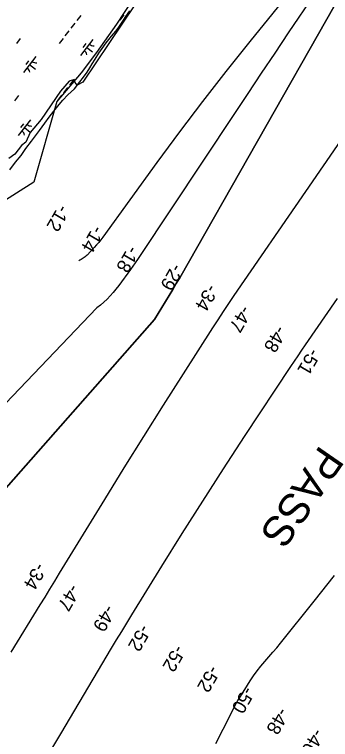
# Model space of a CAD drawing. Extents: x 3888273 to 3909528, y 158682 to 181032.
# Drawn here: x 3899572 to 3900353, y 169134 to 170923 of the extents above; entities that cross this region are included whole.
import ezdxf

# ---------------------------------------------------------------- set-up
doc = ezdxf.new("R2010")
doc.units = 0
for name, color, linetype in [('V-RIVR-EDGE', 7, 'Continuous'), ('V-RIVR-IDEN', 7, 'Continuous'), ('V-RIVR-RANG', 7, 'Continuous'), ('V-RRAP-FSHR', 7, 'Continuous'), ('V-TOPO-DPTH', 7, 'Continuous'), ('V-TOPO-MAJR', 7, 'Continuous'), ('V-TOPO-MINR', 7, 'Continuous'), ('V-WETL-SWMP', 7, 'Continuous')]:
    doc.layers.add(name, color=color, linetype=linetype)

msp = doc.modelspace()

# ---------------------------------------------------------------- linework, layer by layer
at = {"layer": 'V-RIVR-EDGE'}
msp.add_lwpolyline([(3900395.1, 172036.4), (3900253.9, 171678.7), (3900157.2, 171435.2), (3900080.1, 171257.8), (3900063.4, 171231.7), (3900050.4, 171212.2), (3900019.7, 171182.5), (3899994.6, 171143.5), (3899976, 171098.9), (3899921.2, 171023.6), (3899901.7, 170995.7), (3899740.9, 170756), (3899727, 170748.5), (3899721.4, 170755.1), (3899720.5, 170762.5), (3899706.6, 170758.8), (3899685.2, 170733.7), (3899637.8, 170664), (3899610.8, 170631.5), (3899599.7, 170608.2), (3899589.5, 170599.9), (3899572.7, 170578.5), (3899557.9, 170567.4)], dxfattribs=at)
at = {"layer": 'V-RRAP-FSHR'}
msp.add_lwpolyline([(3900345, 171972), (3900308.9, 171879.2), (3900156.1, 171475.9), (3900123.1, 171393.6), (3900080.8, 171288.9), (3899961.8, 171111.1), (3899882.3, 170989.1), (3899823.6, 170898.7), (3899774.2, 170829.5), (3899736.4, 170779.3), (3899676.3, 170708), (3899619.4, 170509.4), (3899413.7, 170379.3)], dxfattribs=at)
at = {"layer": 'V-TOPO-DPTH'}
for points in [[(3899439.6, 169630.1), (3899917.5, 170170.5), (3899935.8, 170199.9), (3899963.2, 170244.7), (3899967.5, 170251.8), (3899971.7, 170258.9), (3899975.9, 170266.1), (3899980.1, 170273.2), (3900364.6, 170948), (3900888.2, 171578.3), (3900889.3, 171579.9), (3900890.3, 171581.6), (3900892.5, 171584.8), (3900894.6, 171588.1), (3900895.7, 171589.7), (3900896.8, 171591.3), (3901374.6, 172277.6)], [(3899439.6, 169630.1), (3899917.5, 170170.5), (3899935.8, 170199.9), (3899963.2, 170244.7), (3899967.5, 170251.8), (3899971.7, 170258.9), (3899975.9, 170266.1), (3899980.1, 170273.2), (3900364.6, 170948), (3900888.2, 171578.3), (3900889.3, 171579.9), (3900890.3, 171581.6), (3900892.5, 171584.8), (3900894.6, 171588.1), (3900895.7, 171589.7), (3900896.8, 171591.3), (3901374.6, 172277.6)], [(3900313.7, 170974.2), (3900248.6, 170877.6), (3900215.2, 170827.9), (3900181.8, 170778.1), (3900148.6, 170728.2), (3900115.3, 170678.4), (3899881.1, 170326.1), (3899875.6, 170318), (3899870.1, 170309.9), (3899864.4, 170301.9), (3899858.7, 170294), (3899829.4, 170254.2), (3899822.6, 170245.4), (3899815.6, 170236.9), (3899808.2, 170228.7), (3899800.5, 170220.7), (3899792.5, 170213.1), (3899784.2, 170205.7), (3899775.7, 170198.7), (3899322.9, 169727)], [(3900378.7, 170612.9), (3900334.8, 170549.4), (3900290.9, 170485.9), (3900114.1, 170229.3), (3900100.7, 170209.5), (3900087.4, 170189.8), (3900074.3, 170169.8), (3900061.3, 170149.8), (3899988.5, 170036.1), (3899939.4, 169959), (3899890.7, 169881.7), (3899842.3, 169804.1), (3899794.3, 169726.4), (3899682.5, 169544), (3899670.5, 169524.4), (3899658.6, 169504.9), (3899646.6, 169485.4), (3899634.6, 169465.9), (3899562.8, 169349.4)], [(3900378.7, 170612.9), (3900334.8, 170549.4), (3900290.9, 170485.9), (3900114.1, 170229.3), (3900100.7, 170209.5), (3900087.4, 170189.8), (3900074.3, 170169.8), (3900061.3, 170149.8), (3899988.5, 170036.1), (3899939.4, 169959), (3899890.7, 169881.7), (3899842.3, 169804.1), (3899794.3, 169726.4), (3899682.5, 169544), (3899670.5, 169524.4), (3899658.6, 169504.9), (3899646.6, 169485.4), (3899634.6, 169465.9), (3899562.8, 169349.4)]]:
    msp.add_lwpolyline(points, dxfattribs=at)
at = {"layer": 'V-TOPO-MAJR'}
for points in [[(3900369.6, 170222.2), (3900290.5, 170107.8), (3900281.3, 170094.4), (3900272.1, 170081), (3900263.1, 170067.5), (3900254.1, 170054), (3900139.9, 169881.2), (3900088, 169801.9), (3900036.5, 169722.2), (3899985.8, 169642.1), (3899935.5, 169561.7), (3899861.1, 169441.4), (3899848.5, 169420.9), (3899835.9, 169400.4), (3899823.5, 169379.8), (3899811.1, 169359.1), (3899685.2, 169147.8), (3899642.1, 169075.2)], [(3900069.6, 169123.9), (3900087.6, 169159.2), (3900118.1, 169219), (3900120.9, 169224.4), (3900123.8, 169229.7), (3900126.9, 169235), (3900130.1, 169240.1), (3900154.5, 169278.6), (3900162.8, 169291), (3900171.6, 169303.1), (3900180.9, 169314.8), (3900190.6, 169326.2), (3900200.5, 169337.5), (3900210.3, 169348.9), (3900219.9, 169360.4), (3900229.4, 169371.9), (3900312.7, 169474.9), (3900362.9, 169538.7)]]:
    msp.add_lwpolyline(points, dxfattribs=at)
at = {"layer": 'V-TOPO-MINR'}
for points in [[(3901374.6, 172277.6), (3900896.8, 171591.3), (3900895.7, 171589.7), (3900894.6, 171588.1), (3900892.5, 171584.8), (3900890.3, 171581.6), (3900889.3, 171579.9), (3900888.2, 171578.3), (3900364.6, 170948), (3899980.1, 170273.2), (3899975.9, 170266.1), (3899971.7, 170258.9), (3899967.5, 170251.8), (3899963.2, 170244.7), (3899935.8, 170199.9), (3899917.5, 170170.5), (3899439.6, 169630.1)], [(3900267.2, 170996.8), (3900153.3, 170856.4), (3900094.5, 170782.7), (3900036.6, 170708.5), (3899979.8, 170633.3), (3899923.9, 170557.5), (3899790.3, 170373.7), (3899785.3, 170367.1), (3899780.1, 170360.6), (3899774.7, 170354.3), (3899769.1, 170348.2), (3899751.2, 170329.4), (3899748.9, 170327.2), (3899746.6, 170325.2), (3899744.1, 170323.4), (3899741.5, 170321.7), (3899738.9, 170320.1), (3899736.2, 170318.4), (3899733.7, 170316.7), (3899731.1, 170314.9)], [(3900313.7, 170974.2), (3900248.6, 170877.6), (3900215.2, 170827.9), (3900181.8, 170778.1), (3900148.6, 170728.2), (3900115.3, 170678.4), (3899881.1, 170326.1), (3899875.6, 170318), (3899870.1, 170309.9), (3899864.4, 170301.9), (3899858.7, 170294), (3899829.4, 170254.2), (3899822.6, 170245.4), (3899815.6, 170236.9), (3899808.2, 170228.7), (3899800.5, 170220.7), (3899792.5, 170213.1), (3899784.2, 170205.7), (3899775.7, 170198.7), (3899322.9, 169727)], [(3900378.7, 170612.9), (3900334.8, 170549.4), (3900290.9, 170485.9), (3900114.1, 170229.3), (3900100.7, 170209.5), (3900087.4, 170189.8), (3900074.3, 170169.8), (3900061.3, 170149.8), (3899988.5, 170036.1), (3899939.4, 169959), (3899890.7, 169881.7), (3899842.3, 169804.1), (3899794.3, 169726.4), (3899682.5, 169544), (3899670.5, 169524.4), (3899658.6, 169504.9), (3899646.6, 169485.4), (3899634.6, 169465.9), (3899562.8, 169349.4)]]:
    msp.add_lwpolyline(points, dxfattribs=at)
at = {"layer": 'V-WETL-SWMP'}
for p, q in [((3899842.1, 170921.8), (3899832.3, 170909.1)), ((3899847.4, 170918.1), (3899856.7, 170931.6)), ((3899735.9, 170920.8), (3899726.1, 170908.2)), ((3899830, 170892), (3899840, 170906.7)), ((3899840, 170906.7), (3899847.4, 170918.1)), ((3899721.2, 170901.8), (3899711.3, 170889.2)), ((3899822.2, 170881.8), (3899830, 170892)), ((3899706.4, 170882.9), (3899696.6, 170870.3)), ((3899798.2, 170853.2), (3899811.4, 170869.1)), ((3899811.4, 170869.1), (3899822.2, 170881.8)), ((3899586.2, 170863.7), (3899576.4, 170851.1)), ((3899691.7, 170864), (3899681.9, 170851.3)), ((3899765.8, 170861.5), (3899735.1, 170822)), ((3899748.1, 170851.2), (3899740.7, 170841.8)), ((3899788.5, 170839.4), (3899798.2, 170853.2)), ((3899750.5, 170841.8), (3899764.7, 170830.7)), ((3899780, 170827.5), (3899788.5, 170839.4)), ((3899624.6, 170819), (3899593.9, 170779.6)), ((3899771.1, 170812.9), (3899780, 170827.5)), ((3899606.8, 170808.8), (3899599.5, 170799.3)), ((3899609.2, 170799.3), (3899623.5, 170788.3)), ((3899758, 170791.6), (3899763.4, 170801)), ((3899763.4, 170801), (3899771.1, 170812.9)), ((3899742.5, 170768.6), (3899751.1, 170780.9)), ((3899751.1, 170780.9), (3899758, 170791.6)), ((3899717.5, 170761.6), (3899707.7, 170748.9)), ((3899732.9, 170756.7), (3899742.5, 170768.6)), ((3899702.8, 170742.6), (3899692.9, 170730)), ((3899719.7, 170739.7), (3899732.9, 170756.7)), ((3899691.3, 170711.9), (3899703.3, 170725)), ((3899703.3, 170725), (3899719.7, 170739.7)), ((3899581.8, 170722.7), (3899572, 170710.1)), ((3899688, 170723.7), (3899678.2, 170711.1)), ((3899682, 170700.8), (3899691.3, 170711.9)), ((3899668.8, 170684.6), (3899682, 170700.8)), ((3899657.6, 170670), (3899668.8, 170684.6)), ((3899611.7, 170663.4), (3899581, 170624)), ((3899594, 170653.2), (3899586.6, 170643.7)), ((3899633.6, 170636.3), (3899646.4, 170654.9)), ((3899646.4, 170654.9), (3899657.6, 170670)), ((3899596.4, 170643.7), (3899610.6, 170632.6)), ((3899621.2, 170620.5), (3899633.6, 170636.3)), ((3899613.8, 170610.6), (3899621.2, 170620.5)), ((3899599.9, 170592), (3899613.8, 170610.6)), ((3899587.9, 170575.4), (3899599.9, 170592)), ((3899574, 170558.4), (3899587.9, 170575.4)), ((3899560, 170539.8), (3899574, 170558.4))]:
    msp.add_line(p, q, dxfattribs=at)
for centre, start, end in [((3899733.7, 170819.8), 11.343, 52.8866), ((3899767.6, 170863.4), 231.343, 272.8866), ((3899626.4, 170821), 231.343, 272.8866), ((3899592.5, 170777.4), 11.343, 52.8866), ((3899579.6, 170621.7), 11.343, 52.8866), ((3899613.5, 170665.3), 231.343, 272.8866)]:
    msp.add_arc(centre, 17.6, start, end, dxfattribs=at)

# ---------------------------------------------------------------- texts
at = {"layer": 'V-RIVR-IDEN'}
msp.add_text('PASS', height=75, rotation=235.3849, dxfattribs=at).set_placement((3900327.9, 169862.7))
at = {"layer": 'V-RIVR-RANG'}
for s, rotation, p in [('-12', 239.6983, (3899682.3, 170456.3)), ('-14', 239.6983, (3899768, 170404.8)), ('-18', 239.6983, (3899854.6, 170354.9)), ('-29', 239.84, (3899963.5, 170310.8)), ('-34', 239.84, (3900049.6, 170260.1)), ('-47', 239.84, (3900133, 170207.5)), ('-48', 239.84, (3900219.4, 170157.9)), ('-51', 239.84, (3900302.2, 170101.7)), ('-34', 240.0287, (3899625.4, 169572.5)), ('-47', 240.0287, (3899708.9, 169519.8)), ('-49', 240.0287, (3899796.6, 169468.8)), ('-52', 240.0287, (3899883.4, 169420.3)), ('-52', 240.0287, (3899968.7, 169369.7)), ('-52', 240.0287, (3900054.2, 169319.1)), ('-50', 240.0287, (3900139.8, 169267.2)), ('-48', 240.0287, (3900225.4, 169215.1)), ('-46', 240.0287, (3900312.2, 169163.4))]:
    msp.add_text(s, height=33.5, rotation=rotation, dxfattribs=at).set_placement(p)

doc.saveas('drawing.dxf')
